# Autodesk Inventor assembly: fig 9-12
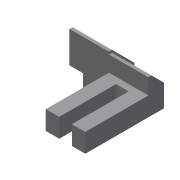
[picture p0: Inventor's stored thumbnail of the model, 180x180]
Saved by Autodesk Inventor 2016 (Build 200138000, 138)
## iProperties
Shininess: 64.0
Length Units: 11269
Angle Units: 11279
Time Units: 11290
Mass Units: 11283
Length Display Precision: 3
Angle Display Precision: 2
Created: 2002-01
Part Number: fig 9-12
Document SubType Name: Assembly
Designer: ***
Density: 0.0
Volumn: 0.0
Area: 0.0
PropertySet Name: Model Information
Control State: 0
Master: False
Checked Out: False
Author: ***
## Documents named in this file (3)
- D:\KAVITA\Autodesk Inventor_ 2016 Project_Kavita\Inventor_Part Files\Inventor_2016_Part\c09_Inv_2016\c09_inv_2016_prt\fig 9-12.iam
- D:\KAVITA\Autodesk Inventor_ 2016 Project_Kavita\Inventor_Part Files\Inventor_2016_Part\c09_Inv_2016\c09_inv_2016_prt\Part3.ipt
- D:\KAVITA\Autodesk Inventor_ 2016 Project_Kavita\Inventor_Part Files\Inventor_2016_Part\c09_Inv_2016\c09_inv_2016_prt\Part4.ipt
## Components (2 placed, 2 different names)
1. Part3:1 — Flush:1, Flush:2, Flush:3, Mate:1
2. Part4:1 — Flush:1, Flush:2, Flush:3, Mate:1
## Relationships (4: Flush 3, Mate 1)
- Flush:1: Part3:1 ↔ Part4:1
- Flush:2: Part3:1 ↔ Part4:1
- Flush:3: Part3:1 ↔ Part4:1
- Mate:1: Part3:1 ↔ Part4:1
